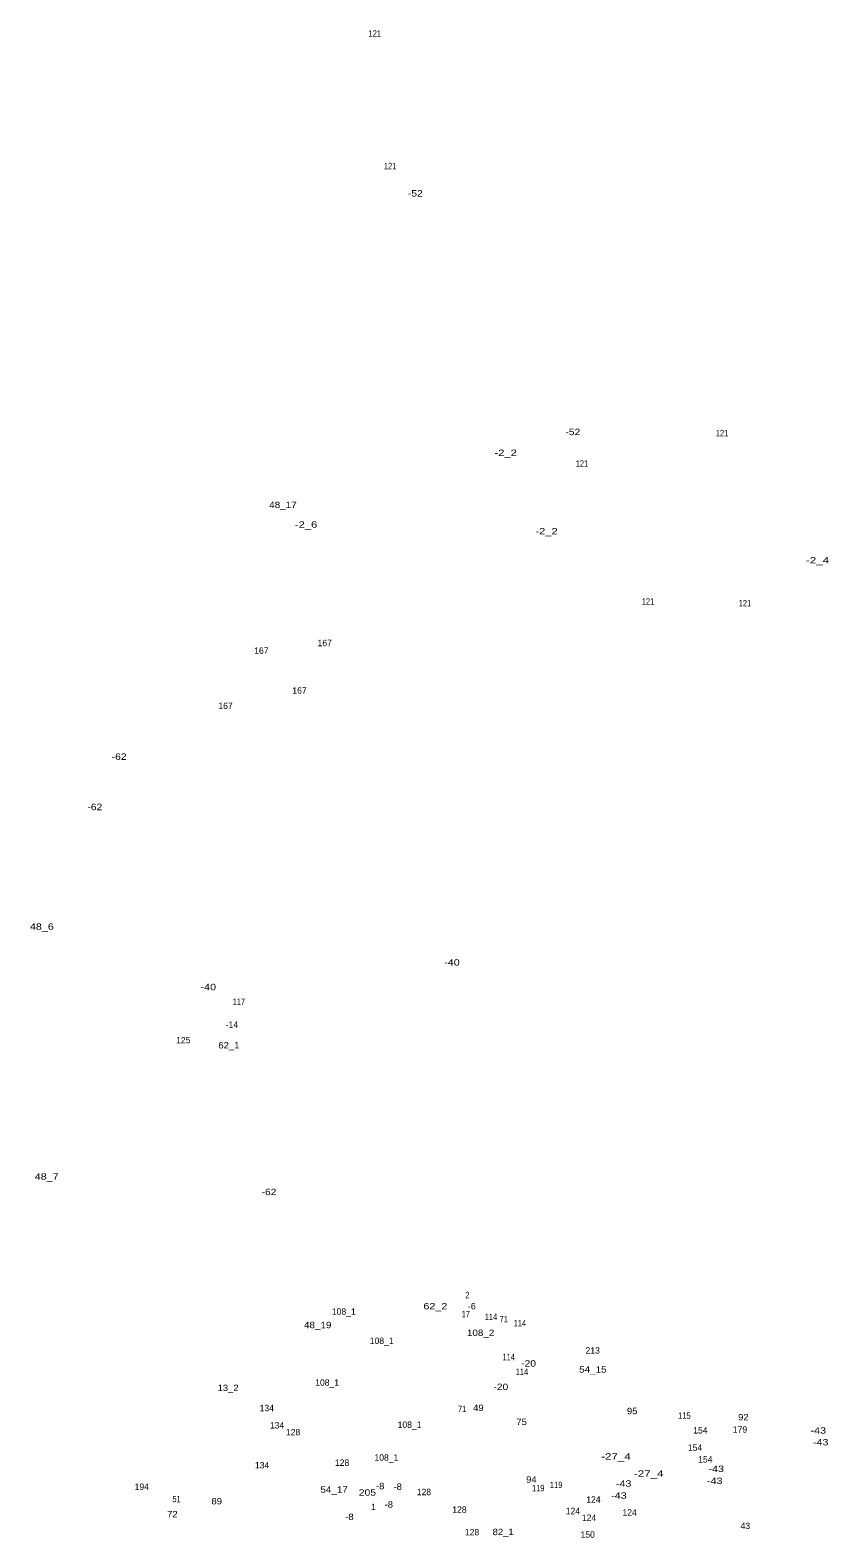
# Model space of a CAD drawing. Extents: x -660405 to -657848, y -988475 to -986360.
# Drawn here: x -658961 to -658464, y -987363 to -986423 of the extents above; entities that cross this region are included whole.
import ezdxf
from ezdxf.enums import TextEntityAlignment as Align

# ---------------------------------------------------------------- set-up
doc = ezdxf.new("R2010")
doc.units = 0
doc.header["$LTSCALE"] = 1.6
doc.layers.add('24', color=7, linetype='Continuous')

msp = doc.modelspace()

# ---------------------------------------------------------------- texts
at = {"layer": '24'}
for s, width, p in [('121', 0.8, (-658746.45, -986427.16)), ('121', 0.8, (-658736.95, -986509.82)), ('-52', 1.2, (-658721.22, -986526.84)), ('-52', 1.2, (-658623.08, -986675.55)), ('121', 0.8, (-658530.13, -986676.28)), ('-2_2', 1.3, (-658664.91, -986688.56)), ('121', 0.8, (-658617.4, -986695.3)), ('48_17', 1.15, (-658803.679, -986721.04)), ('-2_6', 1.3, (-658789.25, -986733.28)), ('-2_2', 1.3, (-658639.449, -986737.47)), ('-2_4', 1.35, (-658470.6, -986755.54)), ('121', 0.8, (-658576.2, -986781.24)), ('121', 0.8, (-658515.87, -986782.34)), ('-62', 1.2, (-658905.73, -986877.97)), ('-62', 1.2, (-658920.86, -986909.35)), ('48_6', 1.25, (-658953.88, -986983.93)), ('-40', 1.25, (-658698.39, -987006.23)), ('-40', 1.25, (-658850.2, -987021.59)), ('117', 0.8, (-658831.12, -987030.76)), ('62_1', 1.1, (-658837.36, -987057.9)), ('48_7', 1.25, (-658950.86, -987139.69)), ('-62', 1.2, (-658812.38, -987149.33)), ('62_2', 1.25, (-658708.73, -987220.55)), ('2', 0.9, (-658688.76, -987213.61)), ('-6', 1.05, (-658686.01, -987220.54)), ('17', 0.85, (-658689.731, -987225.46)), ('114', 0.8, (-658674.059, -987227.16)), ('71', 0.85, (-658666.16, -987228.63)), ('48_19', 1.15, (-658782.02, -987232.29)), ('108_2', 1.15, (-658680.53, -987237.16)), ('114', 0.8, (-658656.079, -987231.21)), ('114', 0.8, (-658663.03, -987252.23)), ('-20', 1.2, (-658650.66, -987256.22)), ('114', 0.8, (-658654.799, -987261.45)), ('54_15', 1.15, (-658610.579, -987259.95)), ('13_2', 1.1, (-658837.83, -987271.44)), ('-20', 1.2, (-658667.93, -987270.85)), ('71', 0.85, (-658692, -987284.56)), ('49', 1.1, (-658681.92, -987283.9)), ('95', 1.1, (-658586.09, -987285.9)), ('75', 1.1, (-658655, -987292.67)), ('115', 0.8, (-658553.57, -987288.74)), ('92', 1.1, (-658516.83, -987289.75)), ('-43', 1.25, (-658470.13, -987298)), ('-43', 1.25, (-658468.66, -987305.31)), ('-27_4', 1.35, (-658596.189, -987314.23)), ('-43', 1.25, (-658533.74, -987321.95)), ('-8', 1.1, (-658743.08, -987332.69)), ('-8', 1.1, (-658732.19, -987333.06)), ('94', 1.1, (-658648.92, -987328.59)), ('119', 0.8, (-658633.5, -987331.91)), ('-43', 1.25, (-658591.43, -987331.1)), ('-27_4', 1.35, (-658575.809, -987324.93)), ('-43', 1.25, (-658534.65, -987329.45)), ('51', 0.8, (-658869.97, -987340.78)), ('89', 1.1, (-658844.91, -987342.11)), ('54_17', 1.15, (-658771.799, -987334.82)), ('205', 1.2, (-658751.069, -987336.68)), ('119', 0.8, (-658644.65, -987333.92)), ('-43', 1.25, (-658594.36, -987338.59)), ('72', 1.1, (-658872.58, -987350.19)), ('-8', 1.1, (-658762.26, -987351.88)), ('-8', 1.1, (-658737.73, -987344.13)), ('82_1', 1.1, (-658666.48, -987361.29))]:
    msp.add_text(s, height=4, dxfattribs=dict(at, width=width)).set_placement(p, align=Align.CENTER)
for s, p in [('167', (-658777.66, -986807.12)), ('167', (-658817.14, -986811.88)), ('167', (-658793.38, -986836.75)), ('167', (-658839.44, -986846.26)), ('-14', (-658835.49, -987045.08)), ('125', (-658865.75, -987054.71)), ('108_1', (-658765.74, -987223.86)), ('108_1', (-658742.16, -987242.14)), ('213', (-658610.72, -987248.14)), ('108_1', (-658776.16, -987268.11)), ('134', (-658813.76, -987284.02)), ('134', (-658807.36, -987294.81)), ('108_1', (-658724.79, -987294.43)), ('128', (-658797.38, -987299.07)), ('154', (-658543.63, -987297.92)), ('179', (-658518.96, -987297.4)), ('108_1', (-658739.24, -987314.9)), ('154', (-658546.919, -987308.71)), ('134', (-658816.679, -987319.68)), ('128', (-658766.85, -987318.09)), ('154', (-658540.52, -987316.03)), ('194', (-658891.61, -987333.09)), ('128', (-658715.85, -987336.37)), ('124', (-658610.23, -987341.09)), ('1', (-658747.262, -987345.69)), ('128', (-658693.73, -987347.35)), ('124', (-658623.03, -987348.23)), ('124', (-658612.97, -987352.43)), ('124', (-658587.669, -987349.12)), ('128', (-658685.87, -987361.43)), ('43', (-658515.621, -987357.48)), ('150', (-658613.82, -987362.91))]:
    msp.add_text(s, height=4, dxfattribs=at).set_placement(p, align=Align.CENTER)

doc.saveas('drawing.dxf')
